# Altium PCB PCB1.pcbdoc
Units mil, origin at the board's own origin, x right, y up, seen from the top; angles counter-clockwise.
Board outline 5535 x 5591.53 mil, 2 copper layers (Top Layer, Bottom Layer); 14 components, 5 nets, 16 pads, 17 vias.
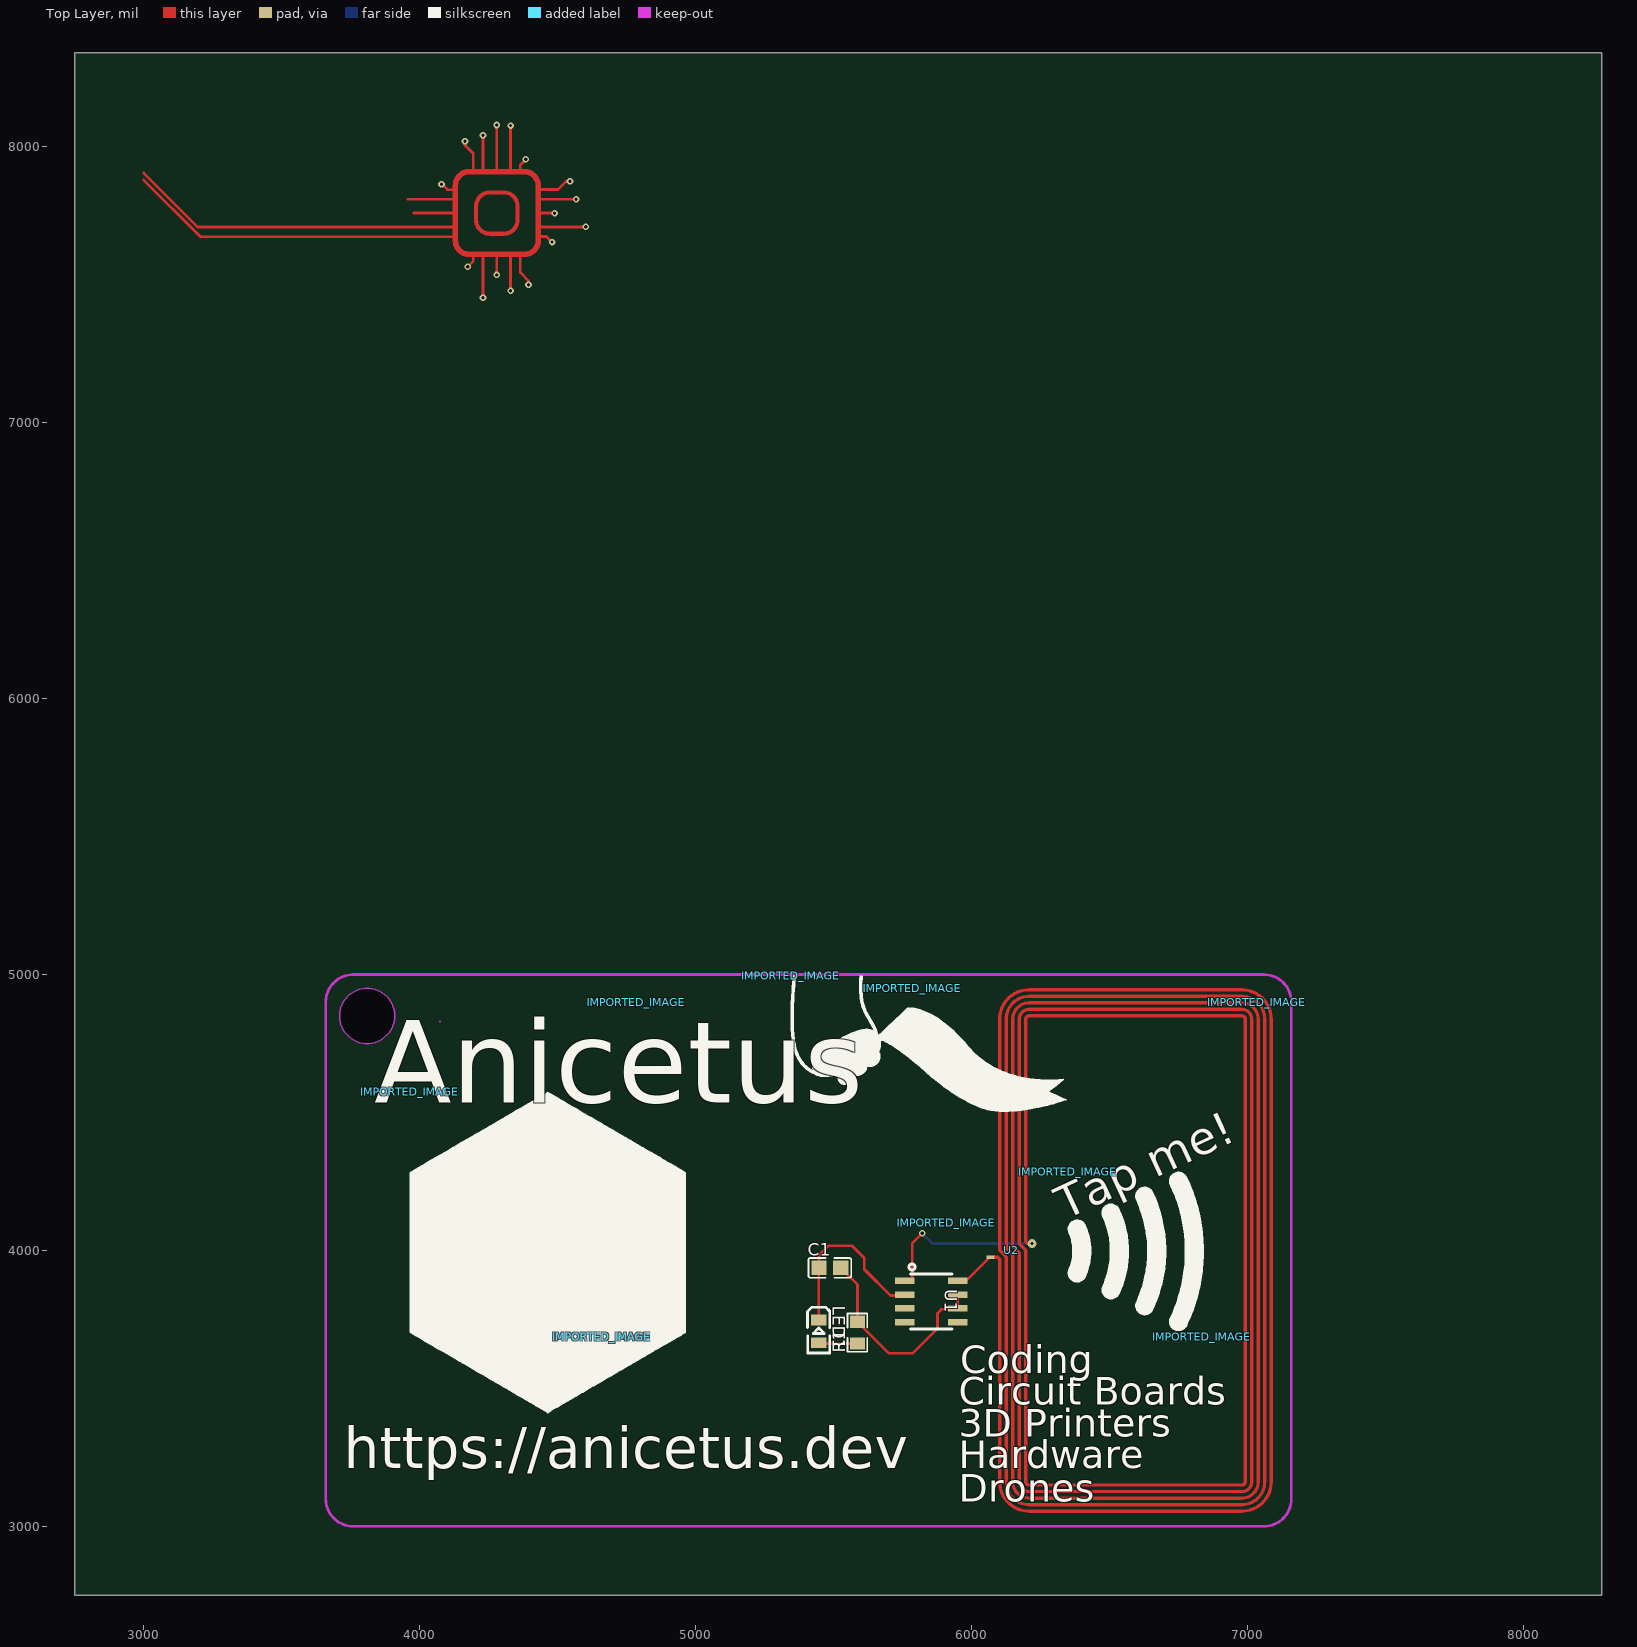
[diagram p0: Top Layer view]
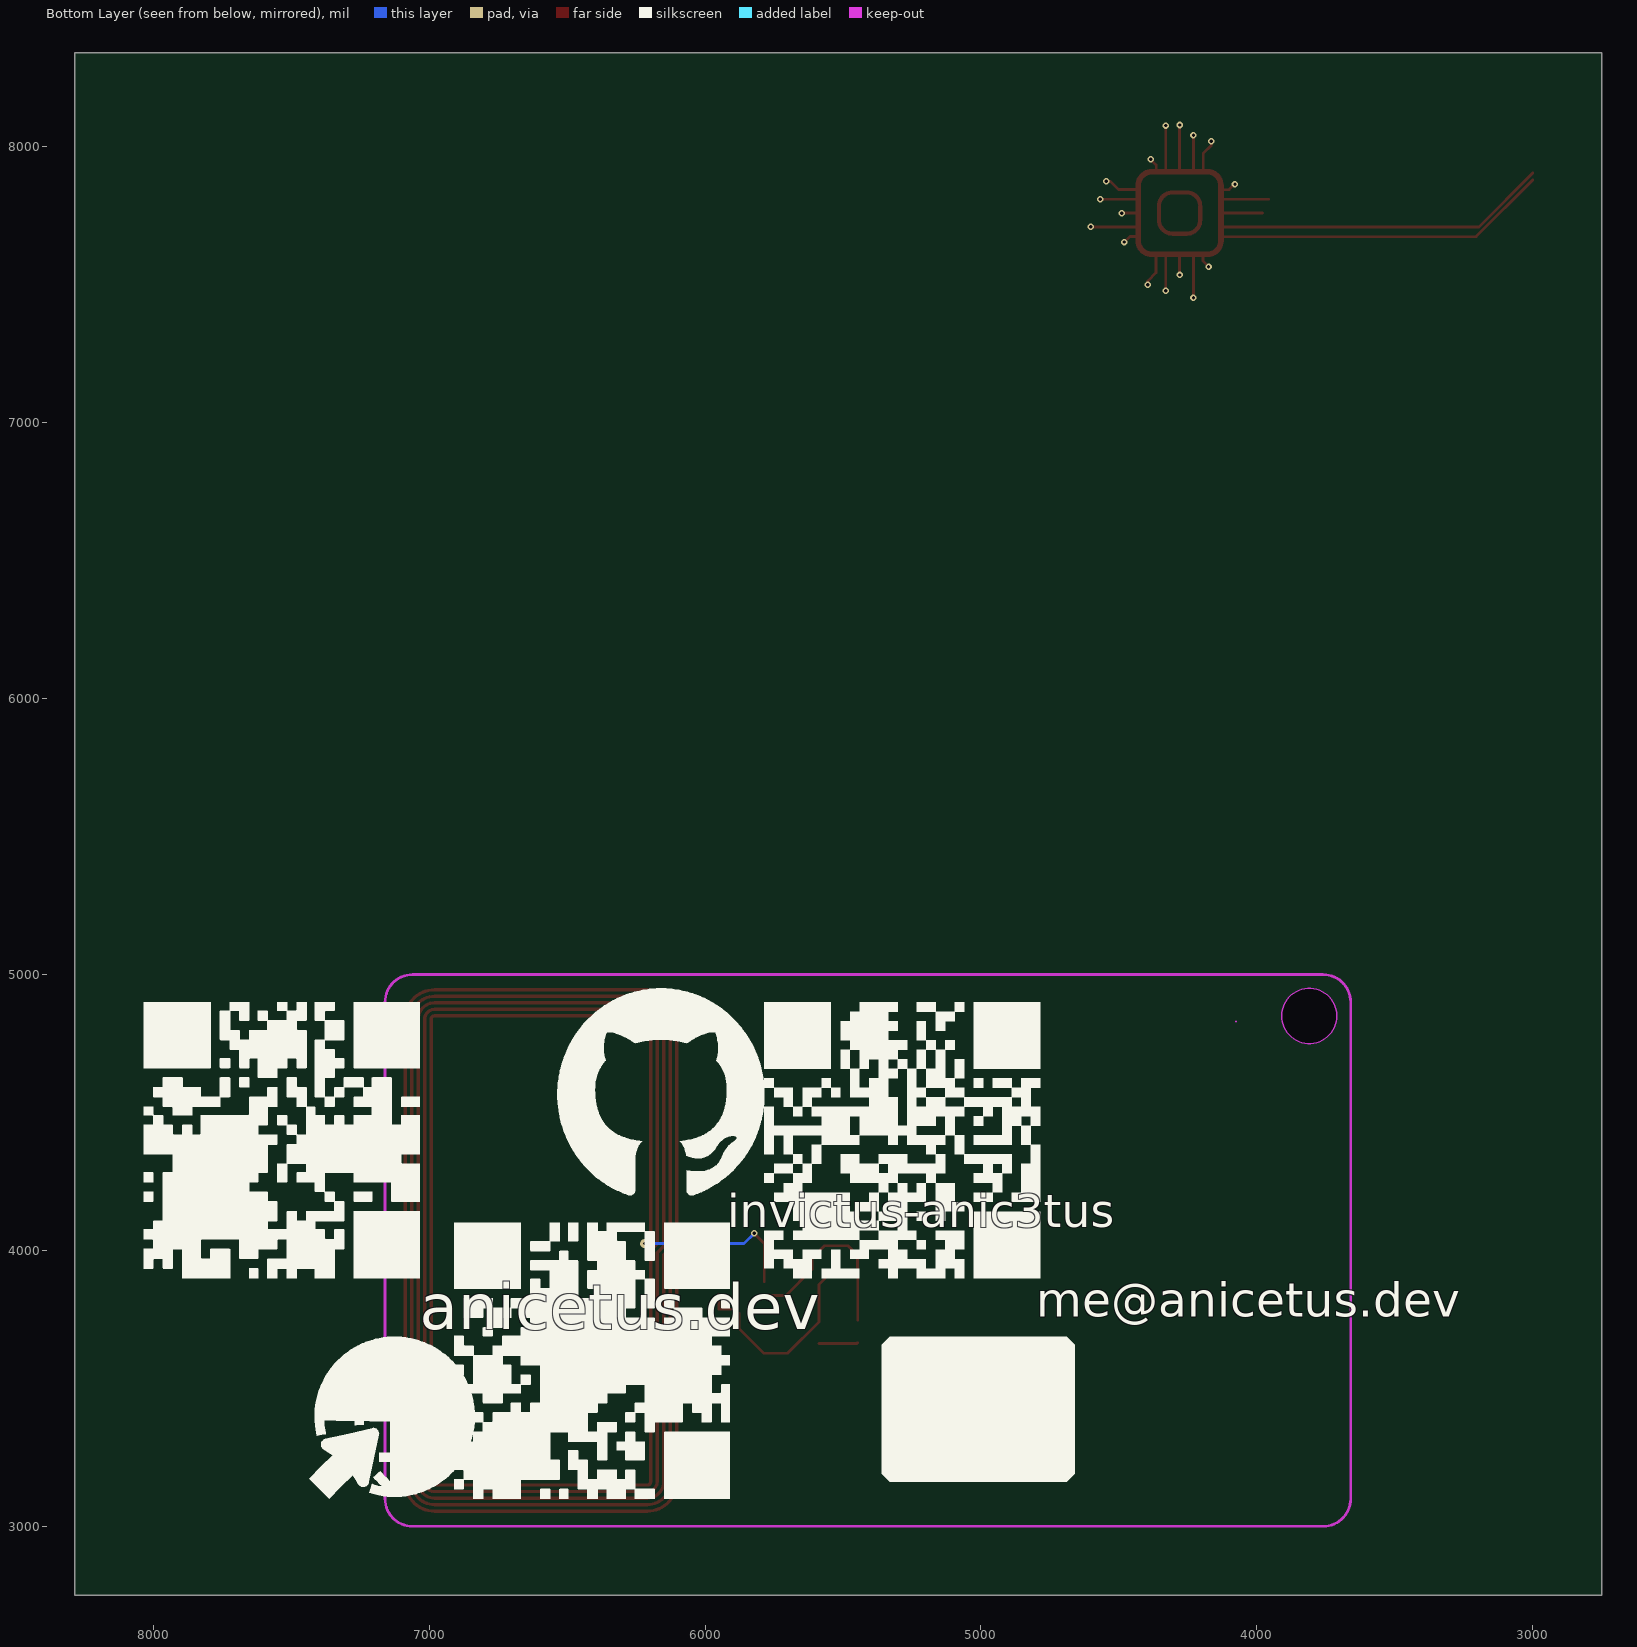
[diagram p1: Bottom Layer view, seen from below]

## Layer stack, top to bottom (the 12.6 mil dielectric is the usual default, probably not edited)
Top Layer: signal copper (thickness not stored)
Dielectric: dielectric 12.6, FR-4, Dk 4.8
Bottom Layer: signal copper (thickness not stored)

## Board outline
8285,2750 2750,2750 2750,8341.53 8285,8341.53
cut-out: 4076,4830 cw(c4075,4830) 4074,4830 cw(c4075,4830)
cut-out: 3910,4850 cw(c3810,4850) 3710,4850 cw(c3810,4850)

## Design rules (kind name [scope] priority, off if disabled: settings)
BoardOutlineClearance copperThickness1oz [All] p0: genericclearance=10 ignorepadtopadclearanceinfootprint=FALSE except(0: Arc-SplitContinuation Track-SplitContinuation SMDPad-SplitContinuation THPad-SplitContinuation Via-SplitContinuation Fill-SplitContinuation Poly-SplitContinuation Region-SplitContinuation Text-SplitContinuation; 6: Track-CutoutEdge SMDPad-CutoutEdge THPad-CutoutEdge Via-CutoutEdge Region-CutoutEdge; 11.8: Track-OutlineEdge SMDPad-OutlineEdge THPad-OutlineEdge Via-OutlineEdge Fill-OutlineEdge Region-OutlineEdge Poly-OutlineEdge Text-OutlineEdge Fill-CutoutEdge)
BoardOutlineClearance copperThickness2oz [All] p0: genericclearance=10 ignorepadtopadclearanceinfootprint=FALSE except(0: Arc-SplitContinuation Track-SplitContinuation SMDPad-SplitContinuation THPad-SplitContinuation Via-SplitContinuation Fill-SplitContinuation Poly-SplitContinuation Region-SplitContinuation Text-SplitContinuation; 6: Track-CutoutEdge SMDPad-CutoutEdge THPad-CutoutEdge Via-CutoutEdge Region-CutoutEdge; 11.8: Track-OutlineEdge SMDPad-OutlineEdge THPad-OutlineEdge Via-OutlineEdge Fill-OutlineEdge Region-OutlineEdge Poly-OutlineEdge Text-OutlineEdge Fill-CutoutEdge)
Clearance copperThickness1oz [(InNet('$1N612') OR InNet('$1N629') OR InNet('$1N653') OR InNet('$1N606') OR InNet('$1N601'))] p1: gap=7 ignorepadtopadclearanceinfootprint=FALSE except(4: Track-Track; 6: Track-SMDPad SMDPad-SMDPad Track-THPad SMDPad-THPad THPad-THPad Track-Via SMDPad-Via THPad-Via Via-Via SMDPad-Fill THPad-Fill Via-Fill Fill-Fill Track-Region SMDPad-Region THPad-Region Via-Region Region-Region Track-Poly SMDPad-Poly THPad-Poly Via-Poly Fill-Poly Region-Poly Poly-Poly Track-Text SMDPad-Text THPad-Text Via-Text Fill-Text Region-Text Poly-Text Text-Text; 6.9: Track-Hole SMDPad-Hole THPad-Hole Via-Hole Fill-Hole Region-Hole Poly-Hole Text-Hole Sheet-Hole; 11.8: Track-Fill Fill-Region Track-Sheet SMDPad-Sheet THPad-Sheet Via-Sheet Fill-Sheet Region-Sheet Poly-Sheet Text-Sheet)
Clearance copperThickness2oz [All] p1: gap=7 ignorepadtopadclearanceinfootprint=FALSE except(6: Track-SMDPad SMDPad-SMDPad Track-THPad SMDPad-THPad THPad-THPad Track-Via SMDPad-Via THPad-Via Via-Via SMDPad-Fill THPad-Fill Via-Fill Fill-Fill Track-Region SMDPad-Region THPad-Region Via-Region Region-Region Track-Poly SMDPad-Poly THPad-Poly Via-Poly Fill-Poly Region-Poly Poly-Poly Track-Text SMDPad-Text THPad-Text Via-Text Fill-Text Region-Text Poly-Text Text-Text; 6.9: Track-Hole SMDPad-Hole THPad-Hole Via-Hole Fill-Hole Region-Hole Poly-Hole Text-Hole Sheet-Hole; 8: Track-Track; 11.8: Track-Fill Fill-Region Track-Sheet SMDPad-Sheet THPad-Sheet Via-Sheet Fill-Sheet Region-Sheet Poly-Sheet Text-Sheet)
DiffPairsRouting differentialPair [All] p1: maxuncoupledlength=10 minlimit=6 maxlimit=6 mostfreqgap=6 toplayer_minwidth=5 toplayer_prefwidth=10 toplayer_maxwidth=100 bottomlayer_minwidth=5 bottomlayer_prefwidth=10 bottomlayer_maxwidth=100
PasteMaskExpansion pasteMaskExpansion [All] p1: expansion=0
PlaneConnect innerPlane [All] p1: planeconnectstyle=Relief reliefexpansion=20 reliefentries=4 reliefconductorwidth=10 reliefairgap=10
PolygonConnect copperRegion [All] p1: connectstyle=Relief reliefentries=4 reliefconductorwidth=10 polygonreliefangle="90 Angle" airgapwidth=10
RoutingVias viaSize [All] p1: viastyle="Through Hole" holewidth=12.0078 minholewidth=11.811 maxholewidth=248.0314 width=24.0158 minwidth=19.685 maxwidth=393.7008
SolderMaskExpansion solderMaskExpansion [All] p1: useseparateexpansions=TRUE expansion=2 expansionbottom=2
Width copperThickness1oz [All] p1: maxlimit=100 minlimit=5 preferedwidth=10
Width copperThickness2oz [All] p1: maxlimit=100 minlimit=8 preferedwidth=10

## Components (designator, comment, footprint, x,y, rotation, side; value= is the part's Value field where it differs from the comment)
C1 "CL21B224KBFNNNE" C0805 5487.08,3937.08 r0 top
IMPORTED_IMAGE "IMPORTED_IMAGE" IMPORTED_IMAGE 6350,4285 r0 top
IMPORTED_IMAGE "IMPORTED_IMAGE" IMPORTED_IMAGE 3965,4575 r0 top
IMPORTED_IMAGE "IMPORTED_IMAGE" IMPORTED_IMAGE 7035,4900 r0 top
IMPORTED_IMAGE "IMPORTED_IMAGE" IMPORTED_IMAGE 5910,4100 r0 top
IMPORTED_IMAGE "IMPORTED_IMAGE" IMPORTED_IMAGE 4785,4900 r0 top
IMPORTED_IMAGE "IMPORTED_IMAGE" IMPORTED_IMAGE 4660,3687.5 r0 top
IMPORTED_IMAGE "IMPORTED_IMAGE" IMPORTED_IMAGE 5785,4950 r0 top
IMPORTED_IMAGE "IMPORTED_IMAGE" IMPORTED_IMAGE 6835,3687.5 r0 top
IMPORTED_IMAGE "IMPORTED_IMAGE" IMPORTED_IMAGE 5345,4995 r0 top
LED1 "KT-0805G" LED0805-R-RD 5447.08,3707.08 r270 top
R1 "FRC0805J470 TS" R0805 5587.08,3702.08 r90 top
U1 "NT3H2111W0FHKH" SO-8_L4.9-W3.9-P1.27-LS6.0-BL 5855,3815 r270 top
U2 "25X48MM_NFC_ANTENNA" 25X48MM_NFC_ANTENNA 6595,4000 r90 top

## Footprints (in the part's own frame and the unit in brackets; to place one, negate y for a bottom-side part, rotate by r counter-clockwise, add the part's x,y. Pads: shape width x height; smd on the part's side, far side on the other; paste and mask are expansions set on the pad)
25X48MM_NFC_ANTENNA [mm]
  rect 0.3x0.75 smd: P$1(-0.635,13.335)
  round 0.808 hole 0.3: P$2(0.635,9.525)
  Top Layer lines w0.3: -0.635,13.462 -0.635,13.335 -0.635,12.665 -0.8,12.5 -21.3,12.5 ccw(c-21.3,9.8) -24,9.8 -24,-9.8 ccw(c-21.3,-9.8) -21.3,-12.5 21.3,-12.5 ccw(c21.3,-9.8) 24,-9.8 24,9.8 ccw(c21.3,9.8) 21.3,12.5 0,12.5 -0.6,11.9 -21.3,11.9 ccw(c-21.3,9.8) -23.4,9.8 -23.4,-9.8 ccw(c-21.3,-9.8) -21.3,-11.9 21.3,-11.9 ccw(c21.3,-9.8) 23.4,-9.8 23.4,9.8 ccw(c21.3,9.8) 21.3,11.9 0.2,11.9 -0.4,11.3 -21.3,11.3 ccw(c-21.3,9.8) -22.8,9.8 -22.8,-9.8 ccw(c-21.3,-9.8) -21.3,-11.3 21.3,-11.3 ccw(c21.3,-9.8) 22.8,-9.8 22.8,9.8 ccw(c21.3,9.8) 21.3,11.3 0.4,11.3 -0.2,10.7 -21.3,10.7 ccw(c-21.3,9.8) -22.2,9.8 -22.2,-9.8 ccw(c-21.3,-9.8) -21.3,-10.7 21.3,-10.7 ccw(c21.3,-9.8) 22.2,-9.8 22.2,9.8 ccw(c21.3,9.8) 21.3,10.7 0.6,10.7 0,10.1 -21.3,10.1 ccw(c-21.3,9.8) -21.6,9.8 -21.6,-9.8 ccw(c-21.3,-9.8) -21.3,-10.1 21.3,-10.1 ccw(c21.3,-9.8) 21.6,-9.8 21.6,9.8 ccw(c21.3,9.8) 21.3,10.1 0.8,10.1 0.635,9.935 0.635,9.525
C0805 [mm]
  rect 1.41x1.35 smd: 1(-1,0) 2(1,0)
  silkscreen extent -1.96,-0.9 1.96,0.9
IMPORTED_IMAGE [mil]
  silkscreen extent 0,-577 492,0
LED0805-R-RD [mm]
  rect 1x1.4 smd: 1(1.05,0) 2(-1.05,0)
  silkscreen extent -2.22,-1.04 1.99,1.01
R0805 [mm]
  rect 1.133x1.377 smd: 1(-1,0) 2(1,0)
  silkscreen extent -1.76,-0.92 1.76,0.92
SO-8_L4.9-W3.9-P1.27-LS6.0-BL [mm]
  rect 0.6x1.8 smd: 1(-1.905,-2.45) 2(-0.635,-2.45) 3(0.635,-2.45) 4(1.905,-2.45) 5(1.905,2.45) 6(0.635,2.45) 7(-0.635,2.45) 8(-1.905,2.45)
  silkscreen extent -3.46,-2.06 2.54,1.91

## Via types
v1: diameter 24.02, hole 12.01, Top Layer to Bottom Layer, 17 vias

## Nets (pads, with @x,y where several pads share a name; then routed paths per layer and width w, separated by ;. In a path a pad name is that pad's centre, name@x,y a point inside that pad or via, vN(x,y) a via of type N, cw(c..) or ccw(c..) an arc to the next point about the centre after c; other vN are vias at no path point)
$1N601: U1.1 U2.P$2 | length 603.6
  Top Layer w10: U1.1@5785.62,3887.08 5785.62,4025.94 v1(5821.76,4062.08)
  Bottom Layer w10: v1(5821.76,4062.08) 5858.84,4025 U2.P$2
$1N606: U1.8 U2.P$1 | length 127.9
  Top Layer w10: U1.8@5978.54,3887.08 6066.46,3975 U2.P$1
$1N612: C1.2 R1.2 U1.6 U1.7 | length 783.1
  Top Layer w10: C1.2 5587.08,3876.45 R1.2 5587.71,3741.45 5702.08,3627.08 5787.08,3627.08 5877.08,3717.08 5877.08,3772.08 5892.08,3787.08 5950,3787.08 5950,3838.54 U1.7
$1N629: C1.1 LED1.2 U1.2 | length 684.7
  Top Layer w10: LED1.2 5447.08,3936.45 C1.1 5447.71,3982.71 5482.08,4017.08 5567.08,4017.08 5612.08,3972.08 5612.08,3932.08 5707.08,3837.08 U1.2@5785.62,3837.08
$1N653: LED1.1 R1.1 | length 141.3
  Top Layer w10: LED1.1 5450.1,3662.71 R1.1
pads on no net: U1.3 U1.4 U1.5
copper on no net: | length 6142.8
  Top Layer w10: 3000,7880 3205.36,7674.64 4058.59,7674.64 4126.79,7674.64 ; 3000,7905 3195,7710 3992.61,7710 4127.65,7710 ; 3957.79,7810 4128.47,7810 ; 3979.19,7760 4129.28,7760 ; v1(4079.52,7865) 4080.74,7865 4100.74,7845 4128.29,7845 ; v1(4165,8020.48) 4165,8006.06 4194.64,7976.41 4194.64,7911.12 ; v1(4175,7565) 4175,7566.22 4195,7586.22 4195,7607.94 ; v1@4230,7459.27 4230,7610 ; 4230,7911.53 v1(4230,8042.39) ; v1(4280,7535.96) 4280,7608.49 ; 4280,7911.17 v1@4280,8079.66 ; v1(4330,7478.09) 4330,7608.05 ; 4330,7912.62 v1(4330,8077.21) ; 4365,7910 4365,7935 ; 4365,7934.26 4385,7954.26 v1(4385,7955.48) ; 4365.36,7609.36 4365.36,7544.07 4395,7514.42 v1(4395,7500) ; 4429.84,7710 v1(4602.21,7710) ; 4429.84,7810 v1(4567.39,7810) ; 4430.48,7760 v1@4488.79,7760 ; 4432.24,7675 4459.26,7675 4479.26,7655 v1(4480.48,7655) ; 4432.28,7845.36 4501.41,7845.36 4531.06,7875 v1(4545.48,7875)
  Top Layer w15: 4205,7735 ccw(c4255,7735) 4255,7685 4305,7685 ccw(c4305,7735) 4355,7735 4355,7785 ccw(c4305,7785) 4305,7835 4255,7835 ccw(c4255,7785) 4205,7785 4205,7735
  Top Layer w20: 4130,7660 ccw(c4180,7660) 4180,7610 4380,7610 ccw(c4380,7660) 4430,7660 4430,7860 ccw(c4380,7860) 4380,7910 4180,7910 ccw(c4180,7860) 4130,7860 4130,7660
  other v1: 4230,7453.27 4489.52,7760 4280,8079.52

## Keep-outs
Board Outline Layer:
  circle w1: c4075,4830 r1
  region: 4076,4830 cw(c4075,4830) 4074,4830 cw(c4075,4830)
  circle w1: c3810,4850 r100
  region: 3910,4850 cw(c3810,4850) 3710,4850 cw(c3810,4850)
  lines w10: 3660,3100 ccw(c3760,3100) 3760,3000 7059.99,3000 ccw(c7059.99,3100) 7159.99,3100 7159.99,4900 ccw(c7059.99,4900) 7059.99,5000 3760,5000 ccw(c3760,4900) 3660,4900 3660,3100

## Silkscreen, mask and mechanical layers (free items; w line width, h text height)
Top Silkscreen Layer:
  text "Anicetus" at 3835,4535 h300
  text "Tap me!" at 6340,4110 h120 r25
  text "Coding" at 5960,3555 h100
  text "Circuit Boards" at 5955,3440 h100
  text "3D Printers" at 5955,3325 h100
  text "https://anicetus.dev" at 3725,3210 h150
  text "Hardware" at 5955,3210 h100
  text "Drones" at 5954.7,3090 h100
Bottom Silkscreen Layer:
  text "invictus-anic3tus" at 5920,4085 h120
  text "me@anicetus.dev" at 4800,3760 h125
  text "anicetus.dev" at 7035,3715 h165
Top Solder Mask Layer:
  lines w10: 3000,7880 3205.36,7674.64 4058.59,7674.64 4129.51,7674.64 ; 3000,7905 3195,7710 3992.61,7710 4129.28,7710 ; 3957.79,7810 4126.84,7810 ; 3979.19,7760 4130,7760 ; 4079.52,7865 4080.74,7865 4100.74,7845 4128.29,7845 ; 4165,8020.48 4165,8006.06 4194.64,7976.41 4194.64,7911.89 ; 4175,7565 4175,7566.22 4195,7586.22 4195,7609.57 ; 4230,7453.27 4230,7605 ; 4230,7911.53 4230,8042.39 ; 4280,7535.96 4280,7610 ; 4280,7911.17 4280,8079.66 ; 4330,7478.09 4330,7609.14 ; 4330,7910.81 4330,8077.21 ; 4365,7911.71 4365,7934.26 4385,7954.26 4385,7955.48 ; 4365.36,7609.95 4365.36,7544.07 4395,7514.42 4395,7500 ; 4429.84,7710 4602.21,7710 ; 4429.84,7810 4567.39,7810 ; 4430.48,7760 4489.52,7760 ; 4432.24,7675 4459.26,7675 4479.26,7655 4480.48,7655 ; 4433.91,7845.36 4501.41,7845.36 4531.06,7875 4545.48,7875
  lines w15: 4205,7735 ccw(c4255,7735) 4255,7685 4305,7685 ccw(c4305,7735) 4355,7735 4355,7785 ccw(c4305,7785) 4305,7835 4255,7835 ccw(c4255,7785) 4205,7785 4205,7735
  lines w20: 4130,7660 ccw(c4180,7660) 4180,7610 4380,7610 ccw(c4380,7660) 4430,7660 4430,7860 ccw(c4380,7860) 4380,7910 4180,7910 ccw(c4180,7860) 4130,7860 4130,7660
Mechanical Layer:
  circle w1: c4075,4830 r1
  circle w1: c3810,4850 r100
